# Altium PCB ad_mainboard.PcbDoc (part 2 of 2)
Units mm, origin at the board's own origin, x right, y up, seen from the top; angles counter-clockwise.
Board outline 51.7 x 87.6 mm, 4 copper layers (Top Layer, Layer 1, Layer 2, Bottom Layer), stack 0.568 mm thick; 187 components, 104 nets, 568 pads, 376 vias.
Unrouted connection lines stored in the file: 1.
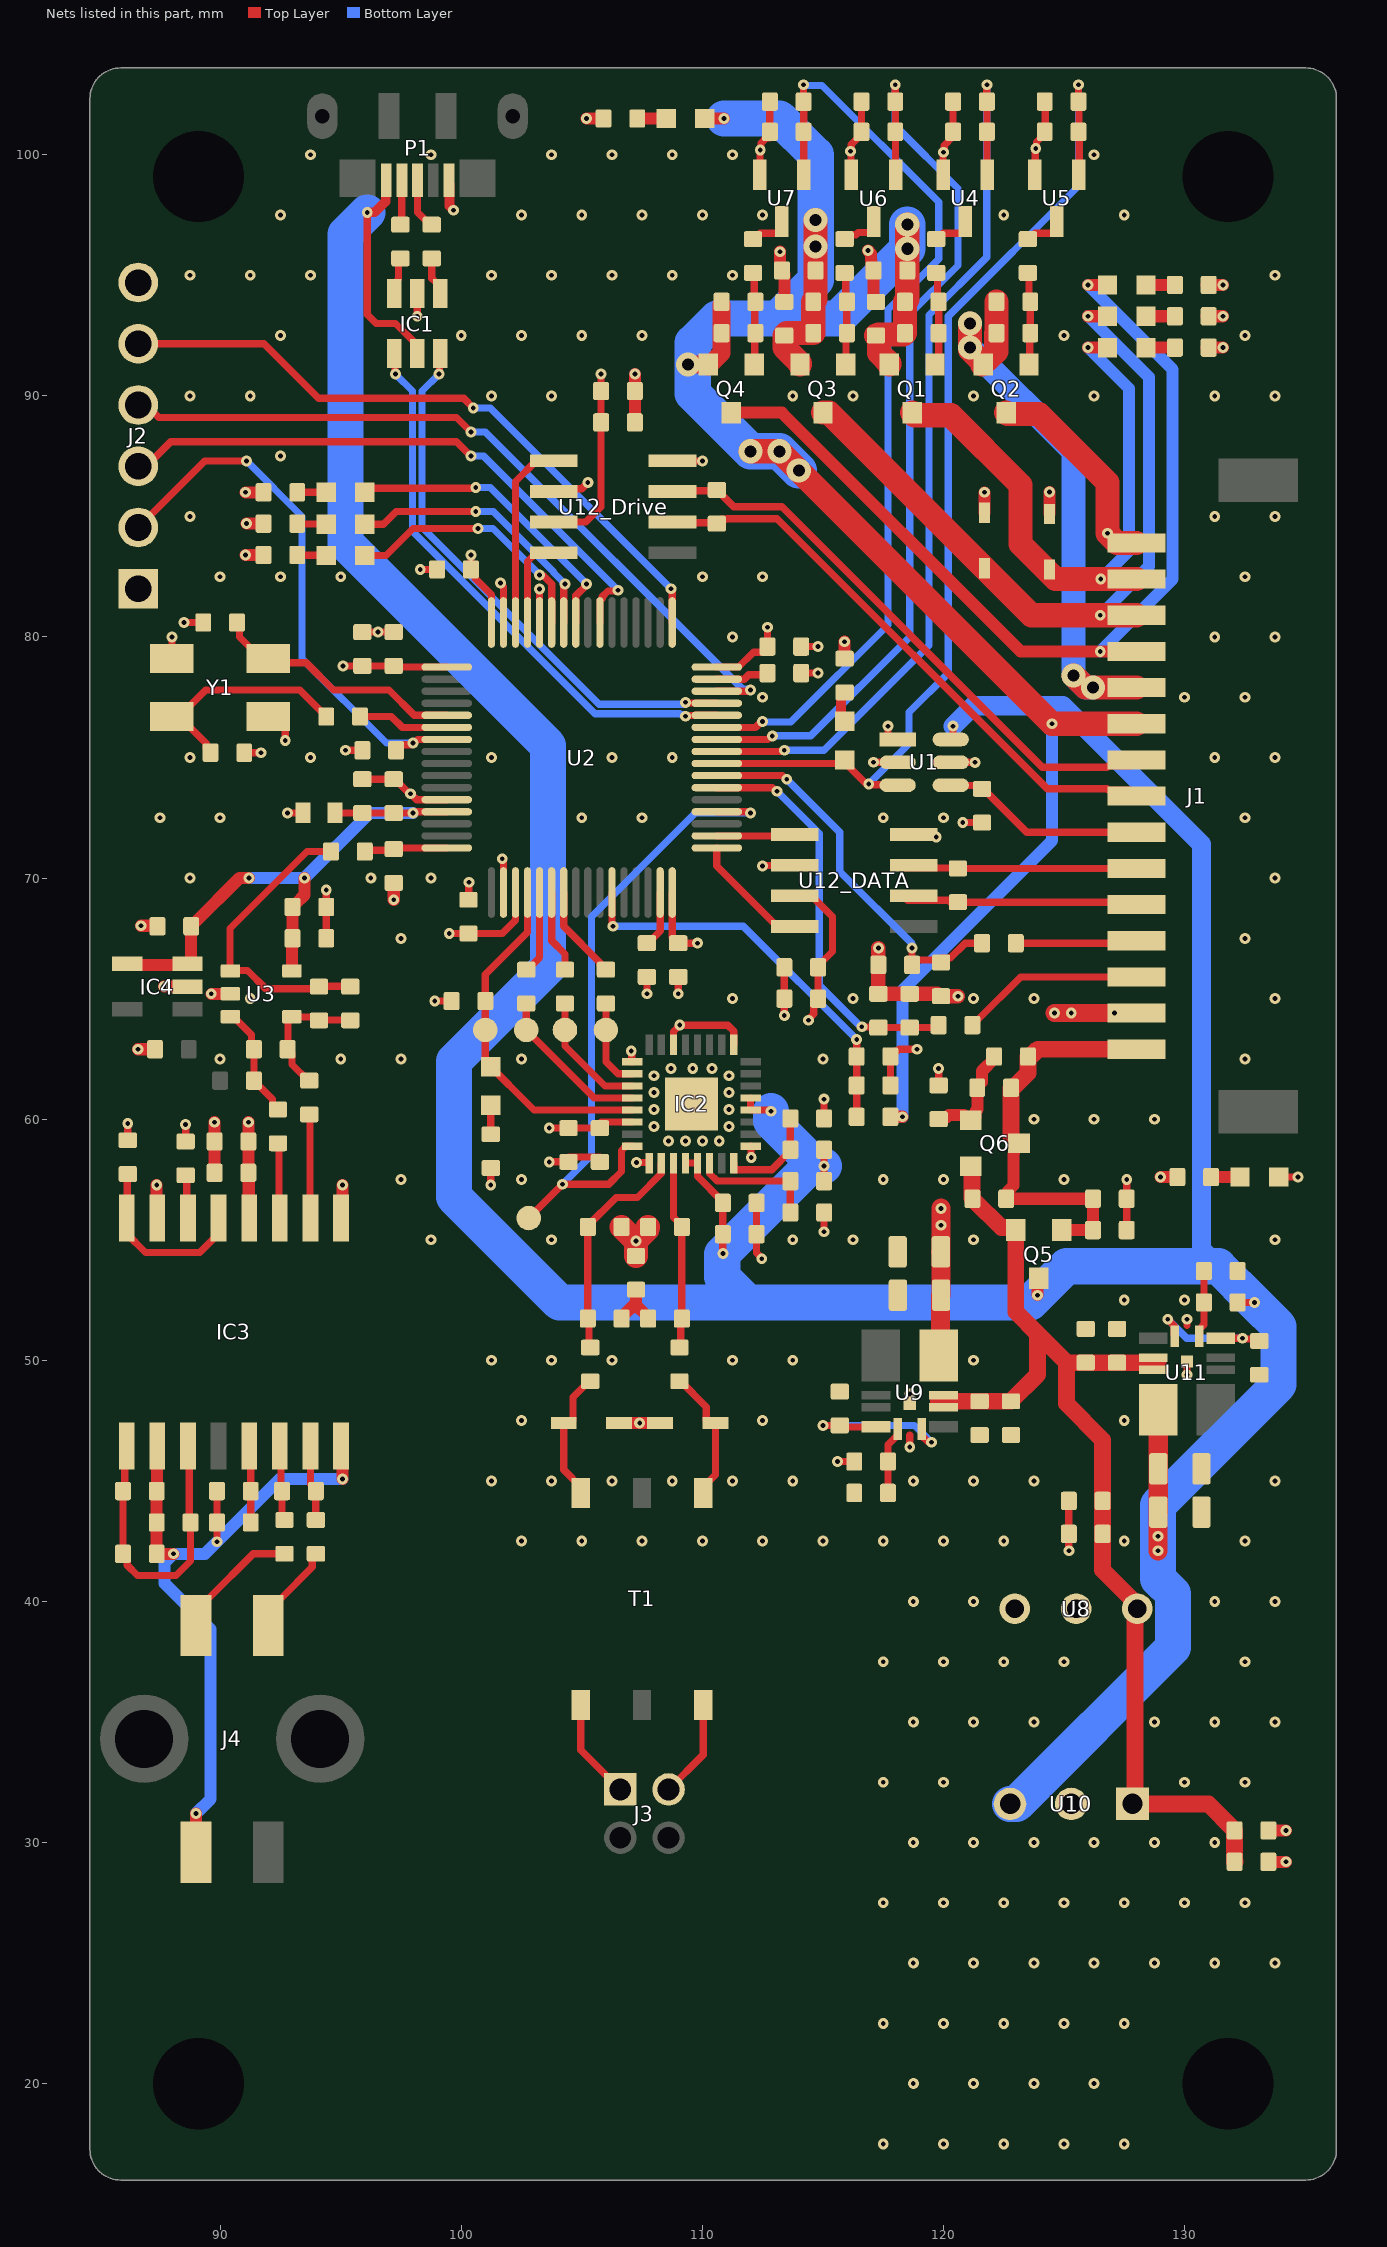
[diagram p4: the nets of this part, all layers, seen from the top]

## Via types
v1: diameter 0.45, hole 0.2, Top Layer to Bottom Layer, tented both sides, 364 vias
v2: diameter 1, hole 0.5, Top Layer to Bottom Layer, tented both sides, 12 vias

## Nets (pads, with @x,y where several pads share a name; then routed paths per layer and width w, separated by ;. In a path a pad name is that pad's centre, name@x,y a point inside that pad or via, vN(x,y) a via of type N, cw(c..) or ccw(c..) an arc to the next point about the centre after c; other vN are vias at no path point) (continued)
3V3: C2.2 C3.1 C4.1 C5.1 C6.1 C7.1 C18.2 C19.1 C27.2 C28.2 C57.2 C58.2 C67_DATA.2 C67_Drive.2 C68_DATA.1 C68_Drive.1 D14.2 IC2.1 IC2.6 IC2.25 IC2.30 IC3.12 J2.1 L1.1 R3.2 R19.2 R29.2 R57.2 U1.1 U1.5 U2.1 U2.19 U2.32 U2.48 U2.64 U8.3 U9.4 U12_DATA.3 U12_Drive.3 | length 56.9
  Top Layer w0.3: v1(88.57,59.775) R29.2@88.57,59.075 R29.2@88.62,59.075 ; v1(92.8,72.7) L1.1@93.437,72.7 ; v1(95.1,78.8) C2.2@95.9,78.8 C3.1@97.2,78.8 97.25,78.75 U2.1@99.4,78.75 ; v1(98.9,64.9) R3.2@99.6,64.9 ; v1(99.5,67.7) C4.1@100.3,67.7 101.7,67.7 102.25,68.25 U2.19@102.25,69.4 ; C7.1@100.4,82.8 v1(100.4,83.4) ; C7.1@100.58,82.911 100.58,82.42 101.25,81.75 U2.64@101.25,80.6 ; v1(101.225,57.275) R19.2@101.225,57.975 ; v1(103.65,59.63) C18.2@104.45,59.63 C19.1@105.75,59.63 ; U12_Drive.3@103.835,84.765 105.165,84.765 105.8,85.4 C68_Drive.1@105.8,88.9 C67_Drive.2@105.8,90.2 v1(105.8,90.9) ; C19.1@105.75,59.83 105.8,59.88 IC2.6@107.1,59.88 ; v1(107.05,62.83) 107.075,62.805 107.075,62.38 IC2.1@107.1,62.38 ; U2.32@108.75,69.4 108.75,67.55 108.77,67.53 108.77,67.48 108.95,67.3 C5.1@109,67.3 v1(109.8,67.3) ; IC2.30@108.8,63.28 108.8,63.639 v1(109.061,63.9) 111.054,63.9 111.3,63.654 IC2.25@111.3,63.08 ; U2.48@110.6,78.75 111.5,78.75 112.12,79.37 112.52,79.37 112.7,79.55 C6.1@112.7,79.6 v1(112.7,80.4) ; U12_DATA.3@113.5,69.16 114.665,69.16 114.675,69.15 114.675,69.125 115.4,68.4 115.4,66.95 114.8,66.35 C68_DATA.1@114.8,65 114.62,64.82 114.62,64.36 114.4,64.141 v1(114.4,64.1) ; v1(115.6,45.8) R57.2@116.3,45.8 ; U1.1@117.7,75.95 v1@117.7,76.3 ; U1.5@119.9,74.925 120.025,74.8 U1.5@120.771,74.8 ; U1.5@120.3,74.8 U1.5@120.771,74.8 ; v1(121.303,74.8) U1.5@120.771,74.8 ; D14.2@133.9,57.6 v1(134.7,57.6)
  Top Layer w0.5: v1(91.17,59.875) C27.2@91.17,59.075 C28.2@91.17,57.775 91.188,57.758 91.188,55.918 IC3.12@91.205,55.9
  Top Layer w0.8: U9.4@119.8,50.2 119.88,50.28 119.88,52.68 C57.2@119.9,52.7 119.895,52.705 119.895,54.495 C58.2@119.89,54.5 119.9,54.51 v1(119.9,55.6) v1(119.9,56.3)
  other v1: 117.7,76.3
3V3A: C8.2 C9.2 C25.2 C26.2 C40.2 IC4.3 IC4.4 L1.2 U2.13 U3.5 | length 24.2
  Top Layer w0.3: L1.2@94.763,72.7 C8.2@95.9,72.7 C9.2@97.2,72.7 v1(98,72.7) 98.041,72.7 98.091,72.75 U2.13@99.4,72.75
  Top Layer w0.5: IC4.4@85.844,66.4 IC4.3@88.6,66.4 ; IC4.3@88.796,66.4 88.8,66.404 C40.2@88.8,68 ; C40.2@88.8,68.05 88.88,68.13 88.93,68.13 90.8,70 v1(91.2,70) ; U3.5@92.975,66.15 92.988,66.163 92.988,67.487 C26.2@93,67.5 C25.2@93,68.8 93,68.85 93.08,68.93 93.13,68.93 93.5,69.3 v1(93.5,70)
  Bottom Layer w0.5: v1(91.2,70) v1(93.5,70) 96.2,72.7 v1(98,72.7)
5V: C20.2 C21.1 C64.2 C65.2 IC1.5 IC2.12 IC2.13 IC2.20 IC2.21 P1.1 Q5.3 R24.2 R25.2 R60.2 U1.6 U10.3 U11.4 | length 175.1
  Top Layer w0.3: v1(96.1,97.6) 96.1,93.375 96.475,93 97.275,93 98.025,92.25 98.025,91.9 IC1.5@98.175,91.75 ; IC2.12@109.3,58.18 IC2.13@109.8,58.18 109.8,57.63 110.85,56.58 C21.1@110.85,56.53 C20.2@110.85,55.23 v1(110.85,54.43) ; IC2.21@112,60.88 IC2.20@112,60.38 112.759,60.38 112.809,60.33 v1(112.85,60.33) ; R24.2@115.05,57.43 v1(115.05,58.055) R25.2@115.05,58.73 ; U1.6@120.3,75.75 120.4,75.85 v1(120.4,76.3) ; R60.2@132.2,52.4 v1(132.9,52.4)
  Top Layer w0.4: v1(96.1,97.6) 96.11,97.61 96.41,97.61 96.863,98.063 P1.1@96.863,98.765
  Top Layer w0.5: v1(123.9,52.7) 123.9,53.35 Q5.3@123.95,53.4
  Top Layer w0.8: v1(128.9,42.1) v1(128.9,42.7) 128.9,43.69 C64.2@128.91,43.7 C65.2@128.91,45.5 128.905,45.505 128.905,47.945 U11.4@128.9,47.95
  Bottom Layer w0.8: v1(120.4,76.3) 121.252,77.152 124.948,77.152 130.7,71.4 130.7,54.6 131.4,53.9
  Bottom Layer w1.5: v1(96.1,97.6) 95.2,96.7 95.2,83.9 103.6,75.5 103.6,66.3 99.7,62.4 99.7,56.773 104.073,52.4 111.873,52.4 ; v1@110.823,54.403 110.823,53.45 111.873,52.4 ; v1(110.85,54.43) 114.475,58.055 114.723,58.055 ; v1(112.85,60.33) 112.85,59.928 114.723,58.055 ; v1(115.05,58.055) 114.723,58.055 ; U10.3@122.76,31.6 123.033,31.6 129.527,38.093 129.527,40.316 128.9,40.942 v1(128.9,42.1) v1(128.9,42.7) 128.9,44 133.9,49 133.9,51.4 v1(132.9,52.4) 131.4,53.9 125.1,53.9 v1(123.9,52.7) 123.6,52.4 111.873,52.4
6822_State: IC2.8 TP5.1 U2.36 | length 27.4
  Top Layer w0.3: TP5.1@102.8,55.9 v1(104.2,57.3) 106.12,57.3 106.65,57.83 106.65,58.705 106.825,58.88 IC2.8@107.1,58.88 ; U2.36@110.6,72.75 111.909,72.75 111.959,72.7 v1(112,72.7)
  Bottom Layer w0.3: v1(104.2,57.3) 105.4,58.5 105.4,68.4 109.7,72.7 v1(112,72.7)
BMS_SD_IN: C43.2 J1.5 Q2.2 R39.2 | length 25
  Top Layer w1: v2(121.1,93) v2(121.1,92) 121.1,91.902 121.6,91.402 121.6,91.302 121.8,91.502 121.85,91.502 122.189,91.84 C43.2@122.189,92.59 ; C43.2@122.2,92.602 R39.2@122.2,93.902 ; v2(125.4,78.4) 125.9,77.9 v2(126.2,77.9) J1.5@128,77.9
  Bottom Layer w1: v2(121.1,93) v2(121.1,92) 125.4,87.7 v2(125.4,78.4) 125.9,77.9 v2(126.2,77.9)
BMS_SD_OUT: J1.1 Q2.3 | length 9.7
  Top Layer w1: Q2.3@122.6,89.302 122.656,89.245 123.955,89.245 126.8,86.4 v1(126.8,84.3) J1.1@127.2,83.9 ; J1.1@127.2,83.9 J1.1@128,83.9 J1.1@127.2,83.9
BMS_Status: C45.2 D1.2 R42.2 U1.3 U2.40 U5.1 | length 43.7
  Top Layer w0.3: U2.40@110.6,74.75 113.579,74.75 113.583,74.754 114.6,74.754 115.5,74.754 115.946,74.754 116.771,73.929 116.871,73.929 116.925,73.875 117.69,73.875 U1.3@117.715,73.9 ; R42.2@125.6,102.202 v1(125.6,102.902) ; R42.2@125.625,102.254 125.625,100.954 125.633,100.947 125.633,99.332 U5.1@125.64,99.325
  Bottom Layer w0.3: v1(116.9,73.9) 118.575,75.575 118.575,76.875 120.2,78.5 120.2,93.3 125.6,98.7 v1(125.6,102.902)
BMS_Status_Out: C1.1 J1.9 U1.4 | length 8.9
  Top Layer w0.3: U1.4@119.928,73.9 119.991,73.837 121.37,73.837 121.507,73.7 121.65,73.7 123.45,71.9 J1.9@128,71.9
CAN_RX_DATA: U2.33 U12_DATA.4 | length 4.7
  Top Layer w0.3: U2.33@110.6,71.25 110.6,70.5 112.99,68.11 113.28,68.11 U12_DATA.4@113.5,67.89
CAN_RX_Drive: U2.61 U12_Drive.4 | length 3.8
  Top Layer w0.3: U2.61@102.75,80.6 102.75,81.783 102.746,81.787 102.746,83.131 103.11,83.495 U12_Drive.4@103.835,83.495
CAN_TX_DATA: U2.34 U12_DATA.1 | length 2.9
  Top Layer w0.3: U2.34@110.6,71.75 113.45,71.75 U12_DATA.1@113.5,71.7
CAN_TX_Drive: U2.62 U12_Drive.1 | length 7.8
  Top Layer w0.3: U2.62@102.25,80.6 102.25,86.445 103.11,87.305 U12_Drive.1@103.835,87.305
CANH_Data_P: J1.10 R62_DATA.2 U12_DATA.7 | length 8.7
  Top Layer w0.3: U12_DATA.7@118.43,70.43 118.445,70.415 120.285,70.415 120.3,70.4 J1.10@127.075,70.4
CANH_Drive_P: J1.7 R62_Drive.2 U12_Drive.7 | length 24.1
  Top Layer w0.3: U12_Drive.7@108.765,86.035 108.797,86.067 110.567,86.067 R62_Drive.2@110.6,86.1 111.3,85.4 113.3,85.4 124.1,74.6 126.774,74.6 126.824,74.65 127.75,74.65 J1.7@128,74.9
CANL_Data_N: J1.11 R62_DATA.1 U12_DATA.6 | length 9.4
  Top Layer w0.3: U12_DATA.6@118.43,69.16 118.51,69.08 120.22,69.08 R62_DATA.1@120.3,69 ; R62_DATA.1@120.6,69 127.9,69 J1.11@128,68.9
CANL_Drive_N: J1.8 R62_Drive.1 U12_Drive.6 | length 24.1
  Top Layer w0.3: U12_Drive.6@108.765,84.765 108.797,84.732 R62_Drive.1@110.617,84.732 ; R62_Drive.1@110.6,84.7 110.78,84.88 110.986,84.88 111.006,84.9 113.1,84.9 124.3,73.7 126.774,73.7 126.824,73.65 127.75,73.65 J1.8@128,73.4
Charger: J1.13 R7.2 | length 7.7
  Top Layer w0.3: R7.2@121.2,63.9 121.2,63.95 121.38,64.13 121.43,64.13 123.2,65.9 J1.13@128,65.9
Charger_mcu: C10.1 R7.1 R8.1 U2.38 | length 16.8
  Top Layer w0.3: U2.38@110.6,73.75 112.909,73.75 113.059,73.6 v1(113.1,73.6) ; v1(116.614,63.836) 116.632,63.818 117.282,63.818 C10.1@117.3,63.8 119.7,63.8 R7.1@119.8,63.9
  Bottom Layer w0.3: v1(113.1,73.6) 114.85,71.85 114.85,65.55 v1@116.445,63.955
Contactor_N: D9.1 D11.2 J1.2 Q1.3 | length 25.2
  Top Layer w0.5: v1(126,92) D11.2@126.8,92
  Top Layer w1: Q1.3@118.7,89.302 118.806,89.195 120.305,89.195 123.2,86.3 123.2,83.85 124.65,82.4 J1.2@128,82.4
  Bottom Layer w0.5: v1(126,92) 127.7,90.3 127.7,83.575 v1(126.525,82.4)
Contactor_N_ctr: C44.2 R40.2 U2.41 U4.1 | length 38.5
  Top Layer w0.3: U2.41@110.6,75.25 113.309,75.25 113.359,75.3 v1(113.4,75.3) ; v1(121.8,102.902) R40.2@121.8,102.202 121.807,102.194 121.807,99.28 U4.1@121.815,99.272
  Bottom Layer w0.3: v1(113.4,75.3) 115.043,75.3 119.4,79.657 119.4,93.352 121.8,95.752 v1(121.8,102.902)
Contactor_P: D10.1 D12.2 J1.3 Q3.3 | length 31.6
  Top Layer w0.5: v1(126,93.3) D12.2@126.8,93.3
  Top Layer w1: Q3.3@115,89.302 115.248,89.302 D10.1@121.7,82.85 123.65,80.9 v1(126.5,80.9) J1.3@128,80.9
  Bottom Layer w0.5: v1(126,93.3) 128.52,90.78 128.52,82.92 v1(126.5,80.9)
Contactor_P_ctrl: C48.2 R46.2 U2.42 U6.1 | length 38.2
  Top Layer w0.3: U2.42@110.6,75.75 112.713,75.75 112.861,75.898 v1(112.902,75.898) ; v1(118,102.902) R46.2@118,102.202 118.007,102.194 118.007,99.28 U6.1@118.015,99.272
  Bottom Layer w0.3: v1(112.902,75.898) 114.498,75.898 118.6,80 118.6,93.402 120.6,95.402 120.6,98.6 118,101.2 v1(118,102.902)
Contactor_Pre: D13.2 J1.4 Q4.3 | length 38.7
  Top Layer w0.5: Q4.3@111.2,89.302 113.298,89.302 123.2,79.4 v1(126.5,79.4) J1.4@127.075,79.4 ; v1(126,94.6) D13.2@126.8,94.6
  Bottom Layer w0.5: v1(126,94.6) 129.5,91.1 129.5,82.4 v1(126.5,79.4)
Contactor_Pre_ctr: C50.2 R52.2 U2.43 U7.1 | length 38.5
  Top Layer w0.3: U2.43@110.6,76.25 112.209,76.25 112.459,76.5 v1(112.5,76.5) ; v1(114.2,102.902) R52.2@114.2,102.202 114.207,102.194 114.207,99.28 U7.1@114.215,99.272
  Bottom Layer w0.3: v1(112.5,76.5) 112.529,76.471 113.671,76.471 117.7,80.5 117.7,93.576 119.8,95.676 119.8,98.04 114.967,102.873 114.228,102.873 v1(114.2,102.902)
CSB: D6.1 IC2.5 R3.1 TP4.1 U2.20 | length 14.7
  Top Layer w0.3: U2.20@102.75,69.4 102.75,67.75 101,66 R3.1@101,64.9 101,62.4 103.02,60.38 IC2.5@107.1,60.38
Current_ADC: C35.2 R31.1 U2.16 | length 3.5
  Top Layer w0.3: R31.1@96,71.1 96.05,71.15 97.15,71.15 97.2,71.1 97.35,71.25 U2.16@99.4,71.25
GND: C1.2 C2.1 C3.2 C4.2 C5.2 C6.2 C7.2 C8.1 C9.1 C10.2 C11.1 C12.1 C13.2 C14.2 C15.2 C16.2 C17.2 C18.1 C19.2 C20.1 C21.2 C22.2 C23.1 C24.2 C25.1 C26.1 C27.1 C28.1 C33.2 C35.1 C39.1 C40.1 C42.1 C44.1 C45.1 C47.1 C48.1 C50.1 C51.2 C52.1 C53.2 C54.1 C55.2 C57.1 C58.1 C59.1 C60.1 C61.2 C62.1 C63.2 C64.1 C65.1 C66.1 C67_DATA.1 C67_Drive.1 C68_DATA.2 C68_Drive.2 D7.1 D8.2 D9.2 D10.2 IC1.2 IC2.9 IC2.17 IC2.33 IC3.9 IC3.15 IC4.2 J1.14 J2.6 P1.5 R8.2 R11.1 R12.1 R13.1 R15.1 R16.1 R17.1 R18.1 R26.2 R27.1 R37.1 R40.1 R42.1 R44.1 R46.1 R48.1 R49.1 R50.1 R52.1 R53.1 R55.1 R58.1 R59.1 R61.1 U1.2 U2.12 U2.18 U2.60 U2.63 U3.2 U4.2 U5.2 U6.2 U7.2 U8.2 U9.10 U10.2 U11.10 U12_DATA.2 U12_DATA.8 U12_Drive.2 U12_Drive.8 Y1.2 Y1.4 | length 96.7
  Top Layer w0.3: C33.2@86.17,59.125 v1(86.17,59.825) ; Y1.4@88,79.1 v1(88,80) ; v1(88.5,80.6) C12.1@89.3,80.6 ; U3.2@90.4,65.2 U3.2@90.404,65.204 ; C11.1@91,75.2 v1(91.7,75.2) ; Y1.2@92,76.7 92.25,76.7 92.7,76.25 v1(92.7,75.7) ; C26.1@94.4,67.5 C25.1@94.4,68.8 v1(94.4,69.5) ; v1(95.2,75.3) C13.2@95.9,75.3 ; C8.1@95.9,74.1 C9.1@97.2,74.1 ; C2.1@95.9,80.2 v1(96.55,80.2) C3.2@97.2,80.2 ; C9.1@97.25,74.1 97.821,73.529 97.871,73.529 v1(97.9,73.5) 98.15,73.25 U2.12@99.4,73.25 ; v1(98.175,93.3) IC1.2@98.175,94.224 ; v1(98.3,82.8) C7.2@99,82.8 ; C4.2@100.3,69.1 100.313,69.113 100.313,69.813 v1(100.326,69.826) ; v1(101.634,82.234) 101.634,82.194 101.75,82.078 U2.63@101.75,80.6 ; v1(101.7,70.8) 101.7,70.759 101.75,70.709 U2.18@101.75,69.4 ; v1(103.248,81.989) 103.25,81.987 U2.60@103.25,80.6 ; v1(103.65,58.23) C18.1@104.45,58.23 ; U12_Drive.2@103.835,86.035 103.95,86.15 104.999,86.15 v1(105.25,86.4) ; C18.1@104.45,58.43 C19.2@105.75,58.43 ; v1(107.275,58.205) 107.28,58.199 107.8,58.199 IC2.9@107.8,58.18 ; v1(107.7,65.2) C16.2@107.7,65.9 ; U12_Drive.8@108.765,87.305 108.767,87.303 109.997,87.303 v1(110,87.3) ; v1(109,65.2) C5.2@109,65.9 ; IC2.17@112,58.88 112.013,58.88 112.013,58.419 v1(112.025,58.407) ; C21.2@112.25,56.53 C20.1@112.25,55.23 112.25,54.459 112.466,54.243 v1(112.466,54.214) ; U7.2@112.387,99.132 112.392,99.138 112.392,100.194 v1(112.4,100.202) 112.429,100.23 112.429,100.48 112.653,100.704 112.794,100.704 R52.1@112.794,102.054 ; v1(112.5,70.5) 112.517,70.517 113.398,70.517 U12_DATA.2@113.415,70.5 ; v1(113.4,64.3) C68_DATA.2@113.4,65 C67_DATA.1@113.4,66.3 ; C15.2@114.1,78.5 v1(114.8,78.5) ; C6.2@114.1,79.6 v1(114.8,79.6) ; v1(115.05,55.33) R26.2@115.05,56.13 ; R27.1@115.05,60.03 v1(115.05,60.83) ; v1(116.145,100.147) v1@116.192,100.147 ; U6.2@116.185,99.374 116.165,99.394 116.165,100.119 v1@116.192,100.147 ; R46.1@116.6,102.332 116.6,100.852 116.174,100.425 116.174,100.165 v1@116.192,100.147 ; v1(117.093,74.803) 117.095,74.802 117.7,74.802 U1.2@117.702,74.803 ; R11.1@117.8,61.4 C14.2@117.8,62.7 ; C14.2@117.8,62.6 117.8,62.65 117.98,62.83 118.09,62.83 118.156,62.896 v1@118.876,62.896 ; U12_DATA.8@118.43,71.7 v1(119.7,71.7) ; v1(118.6,46.4) 118.6,46.9 ; U9.10@118.6,48.195 v1(118.6,48.6) ; R58.1@119.808,61.408 119.8,61.417 119.8,62.083 v1@119.808,62.092 ; U4.2@119.97,99.203 119.985,99.218 119.985,100.088 v1(120,100.103) 120.029,100.132 120.029,100.382 120.4,100.753 R40.1@120.4,102.103 ; v1(120.8,72.3) C1.2@121.6,72.3 ; U5.2@123.795,99.354 123.81,99.369 123.81,100.239 v1(123.825,100.254) 123.854,100.283 123.854,100.533 124.225,100.904 R42.1@124.225,102.254 ; v1(125.2,42.1) C52.1@125.2,42.8 C53.2@125.2,44.168 ; C51.2@127.6,55.4 v1(127.6,57.5) ; v1(130.1,49.4) U11.10@130.1,49.955 ; 130.1,51.45 v1(130.1,51.7)
  Top Layer w0.4: P1.5@99.512,98.765 99.512,97.877 99.675,97.714 v1(99.675,97.7)
  Top Layer w0.5: v1(86.6,62.9) C39.1@87.3,62.9 ; v1(86.722,68.022) 87.378,68.022 C40.1@87.4,68 ; v1(87.37,57.275) 87.37,55.925 IC3.15@87.395,55.9 ; v1(87.675,65.5) IC4.2@88.65,65.5 ; v1(89.634,65.2) U3.2@90.425,65.2 ; C28.1@89.77,57.775 C27.1@89.77,59.075 v1(89.77,59.875) ; v1(91.052,83.4) R17.1@91.8,83.4 ; v1(91.052,86) R16.1@91.8,86 ; v1(91.1,84.7) R12.1@91.8,84.7 ; IC3.9@95.015,55.9 95.07,55.955 v1(95.07,57.275) ; v1(97.2,69.1) C35.1@97.2,69.8 ; v1(105.2,101.5) R15.1@105.9,101.5 ; D7.1@106.55,47.4 v1(107.4,47.4) D8.2@108.25,47.4 ; C68_Drive.2@107.2,88.9 C67_Drive.1@107.2,90.2 v1(107.2,90.9) ; v1(113.221,95.979) 113.221,95.279 R44.1@113.3,95.2 113.3,95.15 113.4,95.05 C47.1@113.4,93.9 ; R13.1@115.9,79.1 v1(115.9,79.8) ; v1(116.871,96.029) 117,95.9 117,95.608 117.02,95.588 117.02,95.28 R37.1@117.1,95.2 ; R37.1@117.1,95.15 117.1,93.98 117.18,93.9 C42.1@117.2,93.9 ; D10.2@121.7,85.15 v1(121.7,86) ; D9.2@124.4,85.1 v1(124.4,86.015) ; v1(129,57.6) R55.1@129.7,57.6 ; R48.1@130.9,92 v1(131.6,92) ; R49.1@130.9,93.3 v1(131.6,93.3) ; R50.1@130.9,94.6 v1(131.6,94.6) ; C61.2@133.475,29.2 v1(134.2,29.2) ; C60.1@133.475,30.5 v1(134.2,30.5)
  Top Layer w0.6: C10.2@117.3,65.2 R8.2@118.6,65.2 119.75,65.2 119.85,65.1 R18.1@119.9,65.1 v1(120.6,65.1) ; C10.2@117.3,65.4 C17.2@117.3,66.6 ; C17.2@117.3,66.4 v1(117.3,67.1)
  Top Layer w0.75: v1(124.6,64.4) v1(125.3,64.4) v1(127.1,64.4)
  Top Layer w1: C22.2@106.65,55.53 107.23,54.95 v1(107.25,54.95) ; C24.2@107.25,54.33 v1(107.25,54.95) ; C23.1@107.75,55.53 107.73,55.51 107.73,55.43 v1(107.25,54.95)
  other v1: 117.5,17.5 120,17.5 122.5,17.5 125,17.5 127.5,17.5 118.75,20 121.25,20 123.75,20 126.25,20 117.5,22.5 120,22.5 122.5,22.5 125,22.5 127.5,22.5 118.75,25 121.25,25 123.75,25 126.25,25 128.75,25 131.25,25 133.75,25 117.5,27.5 120,27.5 122.5,27.5 125,27.5 127.5,27.5 130,27.5 132.5,27.5 118.75,30 121.25,30 123.75,30 126.25,30 128.75,30 131.25,30 117.5,32.5 120,32.5 130,32.5 132.5,32.5 118.75,35 121.25,35 123.75,35 128.75,35 131.25,35 133.75,35 117.5,37.5 120,37.5 122.5,37.5 125,37.5 132.5,37.5 118.75,40 121.25,40 131.25,40 133.75,40 102.5,42.5 105,42.5 107.5,42.5 110,42.5 112.5,42.5 115,42.5 117.5,42.5 120,42.5 122.5,42.5 127.5,42.5 132.5,42.5 101.25,45 103.75,45 106.25,45 108.75,45 111.25,45 113.75,45 118.75,45 121.25,45 123.75,45 133.75,45 102.5,47.5 112.5,47.5 127.5,47.5 101.25,50 103.75,50 106.25,50 111.25,50 113.75,50 121.25,50 127.5,52.5 130,52.5 98.75,55 103.75,55 113.75,55 116.25,55 121.25,55 133.75,55 97.5,57.5 102.5,57.5 117.5,57.5 120,57.5 125,57.5 108.6,59.1 109.3,59.1 110,59.1 110.7,59.1 108,59.7 111.1,59.7 123.75,60 126.25,60 128.75,60 108,60.4 111.1,60.4 108,61.1 111.1,61.1 108,61.8 111.1,61.8 108.7,62.1 109.6,62.1 110.4,62.1 119.8,62.1 90,62.5 95,62.5 97.5,62.5 102.5,62.5 115,62.5 132.5,62.5 118.902,62.9 91.25,65 111.25,65 116.25,65 121.25,65 123.75,65 133.75,65 97.5,67.5 132.5,67.5 88.75,70 96.25,70 98.75,70 133.75,70 87.5,72.5 90,72.5 105,72.5 107.5,72.5 117.5,72.5 120,72.5 132.5,72.5 88.75,75 93.75,75 101.25,75 106.25,75 108.75,75 131.25,75 133.75,75 112.5,77.5 130,77.5 132.5,77.5 111.25,80 131.25,80 133.75,80 90,82.5 92.5,82.5 95,82.5 110,82.5 112.5,82.5 132.5,82.5 88.75,85 131.25,85 133.75,85 92.5,87.5 88.75,90 91.25,90 101.25,90 103.75,90 113.75,90 116.25,90 121.25,90 126.25,90 131.25,90 133.75,90 92.5,92.5 100,92.5 102.5,92.5 105,92.5 107.5,92.5 125,92.5 132.5,92.5 88.75,95 91.25,95 93.75,95 101.25,95 103.75,95 106.25,95 108.75,95 111.25,95 133.75,95 92.5,97.5 102.5,97.5 105,97.5 107.5,97.5 110,97.5 112.5,97.5 122.5,97.5 127.5,97.5 93.75,100 98.75,100 103.75,100 106.25,100 108.75,100 111.25,100 126.25,100
GPIO_LED_1: D4.2 U2.57 | length 12.7
  Top Layer w0.3: D4.2@96,86 96.171,86.171 100.571,86.171 v1(100.6,86.2) ; U2.57@104.75,80.6 104.75,81.709 105.2,82.159 v1(105.2,82.2)
  Bottom Layer w0.3: v1(100.6,86.2) 101.2,86.2 v1(105.2,82.2)
GPIO_LED_2: D2.2 U2.58 | length 11.4
  Top Layer w0.3: D2.2@96,84.675 96.775,84.675 97.3,85.2 v1(100.6,85.2) ; U2.58@104.25,80.6 104.25,82.109 104.3,82.159 v1(104.3,82.2)
  Bottom Layer w0.3: v1(100.6,85.2) 101.328,85.2 103.823,82.706 103.823,82.677 v1(104.3,82.2)
GPIO_LED_3: D5.2 U2.59 | length 10.8
  Top Layer w0.3: D5.2@96,83.375 96.875,83.375 98,84.5 v1(100.7,84.5) ; v1(103.252,82.566) 103.281,82.538 103.41,82.538 103.75,82.197 U2.59@103.75,80.6
  Bottom Layer w0.3: v1(100.7,84.5) 101.318,84.5 v1(103.252,82.566)
HSE_IN: C12.2 U2.5 Y1.3 | length 10.6
  Top Layer w0.3: C12.2@90.7,80.6 90.799,80.501 90.799,80.001 91.7,79.1 Y1.3@92,79.1 92.174,78.926 93.574,78.926 94.7,77.8 97,77.8 98.05,76.75 U2.5@99.4,76.75
HSE_OUT: R9.2 U2.6 | length 3.8
  Top Layer w0.3: R9.2@95.8,76.7 97.1,76.7 97.55,76.25 U2.6@99.4,76.25
IM: C22.1 IC2.10 R20.2 R22.2 | length 9.4
  Top Layer w0.3: C22.1@105.25,55.53 R20.2@105.25,51.73 105.3,51.68 105.3,50.58 R22.2@105.35,50.53 ; C22.1@105.25,55.58 106.425,56.754 107.305,56.754 108.3,57.749 IC2.10@108.3,58.18
IM_Out: J3.1 T1.4 | length 4.2
  Top Layer w0.3: T1.4@104.96,35.7 104.96,33.84 J3.1@106.6,32.2
IMD_Status: J1.12 R14.2 | length 5
  Top Layer w0.3: R14.2@123,67.3 127.9,67.3 J1.12@128,67.4
IMD_Status_mcu: C17.1 R14.1 R18.2 U2.39 | length 15.9
  Top Layer w0.3: U2.39@110.6,74.25 113.309,74.25 113.459,74.1 v1(113.5,74.1) ; C17.1@118.7,66.4 v1(118.7,67.1) ; C17.1@118.7,66.6 119.8,66.6 R18.2@119.9,66.5 ; R18.2@119.85,66.65 119.88,66.68 120.28,66.68 120.9,67.3 R14.1@121.6,67.3
  Bottom Layer w0.3: v1(113.5,74.1) 115.7,71.9 115.7,70.273 v1@118.7,67.273
IP: C23.2 IC2.11 R21.1 R23.2 | length 7.8
  Top Layer w0.3: IC2.11@108.8,58.18 108.8,55.93 109.15,55.58 C23.2@109.15,55.53 R21.1@109.15,51.73 109.1,51.68 109.1,50.58 R23.2@109.05,50.53
IP_Out: J3.3 T1.6 | length 4.1
  Top Layer w0.3: J3.3@108.6,32.2 110.04,33.64 T1.6@110.04,35.7
MISO: IC2.3 R5.1 TP2.1 | length 5.2
  Top Layer w0.3: R5.1@104.3,64.8 TP2.1@104.3,63.7 104.3,63.038 105.958,61.38 IC2.3@107.1,61.38
MOSI: IC2.2 R6.1 TP1.1 | length 3.7
  Top Layer w0.3: R6.1@106,64.8 106,62.38 106.5,61.88 IC2.2@107.1,61.88
NetC11_2: C11.2 R9.1 Y1.1 | length 9.4
  Top Layer w0.3: Y1.1@88,76.7 Y1.1@88.3,76.7 ; C11.2@89.6,75.2 89.42,75.38 89.42,75.58 Y1.1@88.3,76.7 ; R9.1@94.396,76.704 94.396,76.754 94.22,76.93 94.17,76.93 93.3,77.8 89.4,77.8 Y1.1@88.3,76.7
NetC15_1: C15.1 U2.47 | length 2.2
  Top Layer w0.3: U2.47@110.6,78.25 111.74,78.25 111.92,78.43 112.63,78.43 C15.1@112.7,78.5
NetC16_1: C16.1 U2.31 | length 2.4
  Top Layer w0.3: C16.1@107.7,67.3 107.75,67.3 108.25,67.8 U2.31@108.25,69.4
NetC24_1: C24.1 R20.1 R21.2 | length 2.3
  Top Layer w0.5: R20.1@106.65,51.73 106.65,51.78 107.25,52.38 ; C24.1@107.25,52.93 107.25,52.38 ; R21.2@107.75,51.73 107.75,51.78 107.25,52.28 107.25,52.38
NetC29_1: C29.1 C34.2 R28.1 R30.2 U3.4 | length 5.4
  Top Layer w0.3: C34.2@92.8,62.9 92.98,62.72 92.98,62.27 93.65,61.6 R30.2@93.7,61.6 ; C34.2@92.813,63.123 92.813,64.238 94.063,64.238 C29.1@94.088,64.213 ; C29.1@94.088,64.113 R28.1@95.388,64.113
NetC29_2: C29.2 R28.2 R31.2 U3.1 | length 12.6
  Top Layer w0.3: C29.2@94.088,65.513 R28.2@95.388,65.513 ; C29.2@94.088,65.562 93.938,65.413 91.888,65.413 91.138,66.163 90.413,66.163 90.413,67.913 93.6,71.1 R31.2@94.6,71.1
NetC30_2: C30.2 C31.2 C32.2 IC3.1 IC3.3 | length 13
  Top Layer w0.3: C30.2@85.97,41.925 C31.2@85.97,44.575 86.048,44.653 86.048,46.373 IC3.1@86.125,46.45 ; C30.2@85.97,41.975 86.15,41.795 86.15,41.495 86.57,41.075 88.17,41.075 88.77,41.675 C32.2@88.77,43.275 88.718,43.328 88.718,46.398 IC3.3@88.665,46.45
NetC33_1: C33.1 IC3.13 IC3.16 | length 7.7
  Top Layer w0.3: C33.1@85.97,57.875 C33.1@86.048,57.798 ; C33.1@86.17,57.725 86.148,57.703 86.148,55.923 IC3.16@86.125,55.9 86.125,55.25 86.9,54.475 89.16,54.475 89.935,55.25 IC3.13@89.935,55.9
NetC34_1: C34.1 R32.2 R34.2 U3.3 | length 4.7
  Top Layer w0.3: U3.3@90.538,64.262 90.675,64.125 91.301,63.499 91.301,62.999 C34.1@91.4,62.9 R34.2@91.4,61.55 ; R34.2@91.4,61.6 R34.2@91.4,61.55 ; R32.2@92.4,60.4 92.35,60.4 92.17,60.58 92.17,60.83 91.63,61.37 91.58,61.37 R34.2@91.4,61.55
NetC36_1: C36.1 IC3.7 R35.2 | length 3.1
  Top Layer w0.3: IC3.7@93.745,46.45 93.745,44.85 C36.1@93.97,44.625 ; R35.2@93.97,43.375 C36.1@93.97,44.575
NetC36_2: C36.2 IC3.6 R33.2 | length 3.2
  Top Layer w0.3: IC3.6@92.473,46.448 IC3.6@92.475,46.45 92.523,46.403 92.523,44.623 C36.2@92.57,44.575 92.57,43.475 R33.2@92.67,43.375
NetC37_1: C37.1 C38.2 IC3.5 | length 3.2
  Top Layer w0.3: IC3.5@91.205,46.45 91.27,46.385 C37.1@91.27,43.275
NetC41_1: C41.1 Q1.1 R36.1 R38.2 | length 3.8
  Top Layer w0.3: Q1.1@119.65,91.378 119.8,91.528 R36.1@119.8,93.901 119.75,93.952 119.75,95.052 R38.2@119.7,95.102
NetC43_1: C43.1 Q2.1 R39.1 R41.2 | length 3.9
  Top Layer w0.3: R41.2@123.5,95.102 123.55,95.052 123.55,93.952 R39.1@123.6,93.902 ; Q2.1@123.55,91.302 123.575,91.327 123.575,92.577 C43.1@123.6,92.602 R39.1@123.6,93.902 ; R39.1@123.6,93.951 R39.1@123.6,93.902
NetC46_1: C46.1 Q3.1 R43.1 R45.2 | length 3.8
  Top Layer w0.3: R45.2@115.9,95.101 115.95,95.051 115.95,93.952 R43.1@116,93.901 ; Q3.1@115.935,91.303 115.96,91.328 115.96,92.578 C46.1@115.985,92.603 ; C46.1@115.985,92.703 R43.1@115.985,93.901
NetC49_1: C49.1 Q4.1 R47.1 R51.2 | length 3.9
  Top Layer w0.3: R51.2@112.1,95.102 112.15,95.052 112.15,93.952 R47.1@112.2,93.902 ; Q4.1@112.15,91.302 112.175,91.327 112.175,92.571 112.169,92.577 R47.1@112.169,93.952
NetC56_2: C56.2 Q6.1 R56.1 R58.2 | length 4.6
  Top Layer w0.5: R58.2@119.8,60 119.88,60.08 120.128,60.08 120.223,60.175 120.857,60.175 121.082,59.95 Q6.1@121.132,59.95 121.182,59.95 121.332,60.1 121.332,60.317 121.408,60.393 C56.2@121.408,61.358 ; C56.2@121.4,61.3 121.4,61.35 C56.2@121.408,61.358 ; C56.2@121.408,61.392 C56.2@121.408,61.358 ; R56.1@122.1,62.5 121.6,62 121.6,61.55 C56.2@121.408,61.358
NetC59_2: C59.2 U9.8 U9.11 | length 7.4
  Top Layer w0.3: v1(115,47.3) C59.2@115.7,47.3 ; 116.112,47.238 U9.8@117.2,47.238 ; U9.11@119.1,47.15 119.1,46.875 119.346,46.629 119.471,46.629 v1(119.5,46.6)
  Bottom Layer w0.3: v1(115,47.3) 118.8,47.3 v1(119.5,46.6)
NetC66_2: C66.2 U11.8 U11.11 | length 5.9
  Top Layer w0.3: v1(129.3,51.7) 129.575,51.425 129.575,51.025 U11.11@129.6,51 ; U11.8@131.5,50.912 v1(132.4,50.912) 132.429,50.883 133.059,50.883 C66.2@133.088,50.912
  Bottom Layer w0.3: v1(129.3,51.7) 130.088,50.912 v1(132.4,50.912)
NetD1_1: D1.1 R13.2 | length 2.1
  Top Layer w0.3: D1.1@115.7,76.7 115.7,77.52 115.88,77.7 R13.2@115.9,77.7 ; D1.1@115.8,76.5 115.8,76.7 R13.2@115.8,77.52
NetD2_1: D2.1 R12.2 | length 1.2
  Top Layer w0.3: R12.2@93.2,84.7 93.212,84.688 94.388,84.688 D2.1@94.4,84.675
NetD3_1: D3.1 R15.2 | length 1.2
  Top Layer w0.5: R15.2@107.3,101.5 D3.1@108.5,101.5
NetD4_1: D4.1 R16.2 | length 1.2
  Top Layer w0.3: R16.2@93.2,86 D4.1@94.4,86
NetD5_1: D5.1 R17.2 | length 1.2
  Top Layer w0.3: R17.2@93.2,83.4 93.212,83.388 94.388,83.388 D5.1@94.4,83.375
NetD6_2: D6.2 R19.1 | length 1.2
  Top Layer w0.3: R19.1@101.225,59.375 D6.2@101.225,60.575
NetD7_2: D7.2 R22.1 T1.3 | length 5.8
  Top Layer w0.3: T1.3@104.96,44.255 104.96,44.745 104.25,45.455 D7.2@104.25,47.4 104.537,47.4 104.637,47.5 104.637,48.467 105.3,49.13 R22.1@105.35,49.13
NetD8_1: D8.1 R23.1 T1.1 | length 5.9
  Top Layer w0.3: R23.1@109.05,49.13 109.1,49.13 110.163,48.067 110.163,47.5 110.262,47.4 D8.1@110.55,47.4 110.55,45.255 110.04,44.745 T1.1@110.04,44.255
NetD11_1: D11.1 R48.2 | length 1.2
  Top Layer w0.5: D11.1@128.4,92 R48.2@129.6,92
NetD12_1: D12.1 R49.2 | length 1.2
  Top Layer w0.5: D12.1@128.4,93.3 R49.2@129.6,93.3
NetD13_1: D13.1 R50.2 | length 1.2
  Top Layer w0.5: D13.1@128.4,94.6 R50.2@129.6,94.6
NetD14_1: D14.1 R55.2 | length 1.2
  Top Layer w0.5: R55.2@131.1,57.6 D14.1@132.3,57.6
NetIC1_1: IC1.1 R1.2 | length 1.5
  Top Layer w0.3: R1.2@98.775,95.7 98.775,94.876 98.951,94.7 98.975,94.7 99.049,94.626 IC1.1@99.049,94.3
NetIC1_3: IC1.3 R2.2 | length 1.6
  Top Layer w0.3: IC1.3@97.149,94.3 97.149,94.6 97.399,94.85 R2.2@97.399,95.75
NetIC3_10: IC3.10 R30.1 | length 4.3
  Top Layer w0.3: R30.1@93.7,60.2 93.723,60.177 93.723,55.923 IC3.10@93.745,55.9
NetIC3_11: IC3.11 R32.1 | length 3.1
  Top Layer w0.3: R32.1@92.4,59 92.438,58.962 92.438,55.938 IC3.11@92.475,55.9
NetIC3_14: IC3.14 R29.1 | length 1.8
  Top Layer w0.3: R29.1@88.57,57.675 88.618,57.628 88.618,55.948 IC3.14@88.665,55.9
NetP1_2: P1.2 R2.1 | length 1.7
  Top Layer w0.3: R2.1@97.399,97.15 97.537,97.288 P1.2@97.537,98.79
NetP1_3: P1.3 R1.1 | length 1.9
  Top Layer w0.3: P1.3@98.187,98.79 98.187,97.612 98.649,97.15 R1.1@98.699,97.15
NetR4_2: R4.2 U2.21 | length 3.5
  Top Layer w0.3: R4.2@102.7,66.2 102.75,66.2 103.25,66.7 U2.21@103.25,69.4
NetR5_2: R5.2 U2.22 | length 3.4
  Top Layer w0.3: U2.22@103.75,69.4 103.75,67.4 104.3,66.85 R5.2@104.3,66.2
NetR6_2: R6.2 U2.23 | length 4
  Top Layer w0.3: U2.23@104.25,69.4 104.25,68 105.77,66.48 105.77,66.38 105.95,66.2 R6.2@106.05,66.2
NetR38_1: R38.1 U4.3 | length 1.7
  Top Layer w0.3: R38.1@119.7,96.502 119.75,96.502 119.993,96.744 120.771,96.744 120.9,96.874 U4.3@120.9,97.229
NetR41_1: R41.1 U5.3 | length 1.7
  Top Layer w0.3: R41.1@123.5,96.5 123.55,96.5 123.794,96.744 124.571,96.744 124.7,96.874 U5.3@124.7,97.229
NetR45_1: R45.1 U6.3 | length 1.7
  Top Layer w0.3: R45.1@115.9,96.502 115.95,96.502 116.13,96.682 116.363,96.682 116.46,96.779 116.971,96.779 117.1,96.909 U6.3@117.1,97.229
NetR51_1: R51.1 U7.3 | length 1.7
  Top Layer w0.3: R51.1@112.1,96.502 112.15,96.502 112.393,96.744 113.171,96.744 113.3,96.874 U7.3@113.3,97.229
NetR57_1: R57.1 R59.2 U9.9 | length 2.8
  Top Layer w0.3: R59.2@117.7,44.5 R57.1@117.7,45.8 117.7,46.5 118.05,46.85 118.075,46.85 118.1,46.875 U9.9@118.1,47.15
NetR60_1: R60.1 R61.2 U11.9 | length 2.8
  Top Layer w0.3: U11.9@130.6,51 130.6,51.275 130.8,51.475 R60.1@130.8,52.4 R61.2@130.8,53.7
NRST: C13.1 J2.2 U2.7 | length 23.2
  Top Layer w0.3: J2.2@86.6,84.54 89.36,87.3 v1(91.1,87.3) ; C13.1@97.3,75.3 97.3,75.35 97.48,75.53 97.889,75.53 97.959,75.6 v1(98,75.6) 98.041,75.6 98.191,75.75 U2.7@99.4,75.75
  Bottom Layer w0.3: v1(91.1,87.3) 93.4,85 93.4,79.1 96.9,75.6 v1(98,75.6)
PHAPOL: IC2.14 R24.1 R26.1 | length 5.2
  Top Layer w0.3: IC2.14@110.3,58.18 110.3,57.749 110.618,57.431 113.648,57.431 R24.1@113.65,57.43 R26.1@113.65,56.13
reg_input: C52.2 C53.1 C54.2 C55.1 C60.2 C61.1 C62.2 C63.1 Q5.2 Q6.2 R54.1 U8.1 U9.2 U9.3 U10.1 U11.2 U11.3 | length 46.7
  Top Layer w0.3: 119.8,48.3 119.8,48.075 119.825,48.05 U9.2@120,48.05 ; U11.3@128.7,49.6 128.7,49.7 cw(c128.9,49.7) 128.9,49.9
  Top Layer w0.7: 119.8,48.3 C55.1@121.5,48.3 C54.2@122.8,48.3 122.81,48.3 122.83,48.32 122.83,48.33 123.9,49.4 123.9,51.1 ; Q6.2@121.132,58.05 121.14,58.05 121.19,58 121.19,56.73 121.2,56.72 R54.1@121.2,56.7 121.22,56.68 121.22,56.67 121.24,56.65 121.25,56.65 122.4,55.5 122.95,55.5 123,55.45 123,52 123.9,51.1 ; 128.9,49.9 C63.1@127.2,49.9 C62.2@125.9,49.9 125.1,49.9 ; C61.1@132.095,29.22 C61.1@132.075,29.2 C60.2@132.075,30.5 132.075,30.51 130.985,31.6 U10.1@127.84,31.6 127.94,31.7 127.94,39.6 U8.1@128.04,39.7 128.04,39.854 126.6,41.294 C52.2@126.6,42.8 C53.1@126.6,44.168 126.6,46.7 125.1,48.2 125.1,49.9 ; 123.9,51.1 125.1,49.9
SCK: IC2.4 R4.1 TP3.1 | length 6.7
  Top Layer w0.3: R4.1@102.7,64.8 TP3.1@102.7,63.7 105.52,60.88 IC2.4@107.1,60.88
SD_Contactors: C41.2 C42.2 C46.2 C47.2 C49.2 D3.2 J1.6 Q1.2 Q3.2 Q4.2 R10.1 R36.2 R37.2 R43.2 R44.2 R47.2 | length 90.4
  Top Layer w0.5: D3.2@110.1,101.5 v1(110.9,101.5) ; R10.1@117.8,60.1 v1(118.3,60.1)
  Top Layer w0.75: v2(109.4,91.3) 110.177,91.3 110.25,91.227 110.8,91.777 C49.2@110.8,92.602 R47.2@110.8,93.777
  Top Layer w1: v2(112,87.7) v2(113.2,87.7) v2(114,86.9) v1(124.5,76.4) J1.6@128,76.4 ; Q3.2@114.05,91.302 114.05,91.352 113.4,92.002 C47.2@113.4,92.5 113.502,92.602 C46.2@114.6,92.602 R43.2@114.6,93.901 114.7,94.002 R44.2@114.7,95.2 v2(114.7,97.3) ; C42.2@117.2,92.5 C42.2@117.25,92.5 ; Q1.2@117.75,91.302 117.75,91.352 117.33,91.771 117.33,92.42 C42.2@117.25,92.5 ; v2(118.5,97.1) v2(118.5,96.1) R37.2@118.5,95.2 118.5,94.002 R36.2@118.4,93.901 C41.2@118.4,92.602 118.349,92.551 117.301,92.551 C42.2@117.25,92.5
  Bottom Layer w0.5: v1(118.3,60.1) 118.3,65.35 124.5,71.55 v1(124.5,76.4)
  Bottom Layer w1.5: v1(110.9,101.5) 113.2,101.5 114.7,100 114.7,94.8 113.102,93.202 ; v2(114,86.9) v2(113.2,87.7) v2(112,87.7) 109.6,90.1 109.6,92.2 110.602,93.202 113.102,93.202 ; v2(118.5,97.1) v2(118.5,96.1) 115.602,93.202 113.102,93.202
  other v2: 114.7,96.2
SD_Contactors_mcu: C14.1 R10.2 R11.2 U2.27 | length 16.8
  Top Layer w0.3: U2.27@106.25,69.4 106.25,68.091 106.3,68.041 v1(106.3,68) ; R10.2@116.4,60.1 R11.2@116.4,61.4 C14.1@116.4,62.7 ; C14.1@116.4,62.6 v1(116.4,63.3)
  Bottom Layer w0.3: v1(106.3,68) 111.7,68 v1(116.4,63.3)
Shunt_N: C30.1 C31.1 C32.1 C37.2 C38.1 IC3.2 IC3.8 J4.3 | length 30.5
  Top Layer w0.3: v1(89.87,42.475) C37.2@89.87,43.275 C38.1@89.87,44.575
  Top Layer w0.5: IC3.2@87.395,46.45 87.383,46.438 87.383,44.588 C31.1@87.37,44.575 C32.1@87.37,43.275 C30.1@87.37,41.975 v1(88.07,41.975) ; J4.3@89,29.6 v1(89,31.2) ; IC3.8@95.015,46.45 95.07,46.395 v1(95.07,45.075)
  Bottom Layer w0.5: v1(89,31.2) 89.6,31.8 89.6,38.845 87.7,40.745 87.7,41.605 v1(88.07,41.975) 89.37,41.975 v1(89.87,42.475) 92.47,45.075 v1(95.07,45.075)
Shunt_N_Kelvin: J4.2 R35.1 | length 3.8
  Top Layer w0.3: J4.2@92,39 92.443,39.443 92.443,40.078 92.485,40.12 92.52,40.12 93.823,41.423 93.823,41.828 R35.1@93.97,41.975
Shunt_P_Kelvin: J4.1 R33.1 | length 5.3
  Top Layer w0.3: J4.1@89,39 89,39.635 89.485,40.12 89.52,40.12 91.375,41.975 R33.1@92.67,41.975
SWCLK: J2.5 U2.49 | length 27.7
  Top Layer w0.3: J2.5@86.6,92.16 91.815,92.16 94.075,89.9 100.1,89.9 v1(100.5,89.5) ; v1(108.7,82) 108.7,81.959 108.75,81.909 U2.49@108.75,80.6
  Bottom Layer w0.3: v1(100.5,89.5) 101.2,89.5 v1(108.7,82)
SWDIO: J2.4 U2.46 | length 31.7
  Top Layer w0.3: J2.4@86.6,89.62 86.931,89.62 87.451,89.1 99.8,89.1 v1(100.4,88.5) ; U2.46@110.6,77.75 111.909,77.75 111.959,77.8 v1(112,77.8)
  Bottom Layer w0.3: v1(100.4,88.5) 101,88.5 111.671,77.829 111.971,77.829 v1(112,77.8)
SWO: J2.3 U2.55 | length 24.7
  Top Layer w0.3: J2.3@86.6,87.08 86.931,87.08 87.951,88.1 99.8,88.1 v1(100.4,87.5) ; U2.55@105.75,80.6 105.75,81.5 105.848,81.598 105.848,81.666 106.089,81.907 106.471,81.907 v1(106.5,81.935)
  Bottom Layer w0.3: v1(100.4,87.5) 100.935,87.5 v1(106.5,81.935)
unreg_V: C51.1 C56.1 J1.15 Q5.1 Q6.3 R53.2 R54.2 R56.2 | length 16.5
  Top Layer w0.5: R54.2@122.6,56.7 R53.2@126.2,56.7 C51.1@126.2,55.4 Q5.1@124.9,55.4 ; R54.2@122.608,56.708 122.68,56.78 122.68,57.022 122.9,57.241 122.9,58.557 122.932,58.589 122.932,58.85 123.082,59 Q6.3@123.132,59
  Top Layer w0.7: Q6.3@123.082,59 122.8,59.282 C56.1@122.8,61.3 122.82,61.32 122.82,61.33 122.92,61.33 123.5,61.91 R56.2@123.5,62.6 ; R56.2@123.52,62.63 123.64,62.63 123.91,62.9 J1.15@127.075,62.9
USB_D_N: IC1.4 U2.44 | length 23.4
  Top Layer w0.3: v1@97.25,90.925 97.25,91.649 IC1.4@97.275,91.674 ; v1(109.3,76.712) 109.329,76.74 109.69,76.74 109.7,76.75 U2.44@110.6,76.75
  Bottom Layer w0.3: v1(97.275,90.9) 97.974,90.201 97.974,84.383 105.545,76.812 109.067,76.812 109.092,76.787 109.184,76.787 109.259,76.712 v1(109.3,76.712)
USB_D_P: IC1.6 U2.45 | length 22.8
  Top Layer w0.3: IC1.6@99.075,91.774 99.1,91.749 v1@99.1,90.925 ; v1(109.3,77.289) 109.329,77.26 109.69,77.26 109.7,77.25 U2.45@110.6,77.25
  Bottom Layer w0.3: v1(99.075,90.9) 98.376,90.201 98.376,84.549 105.712,77.214 109.184,77.214 109.259,77.289 v1(109.3,77.289)
XCVRMD: IC2.16 R25.1 R27.2 | length 4.3
  Top Layer w0.3: IC2.16@111.3,58.18 111.3,57.905 112.875,57.905 113.65,58.68 R25.1@113.65,58.73 R27.2@113.65,60.03
pads on no net: IC2.7 IC2.15 IC2.18 IC2.19 IC2.22 IC2.23 IC2.24 IC2.26 IC2.27 IC2.28 IC2.29 IC2.31 IC2.32 IC3.4 IC4.5 J1.16 J1.17 J3.2 J3.4 J4.4 J4.5 J4.6 MH1. MH2. MH3. MH4. P1.4 P1.6 T1.2 T1.5 U2.2 U2.3 U2.4 U2.8 U2.9 U2.10 U2.11 U2.14 U2.15 U2.17 U2.24 U2.25 U2.26 U2.28 U2.29 U2.30 U2.35 U2.37 U2.50 U2.51 U2.52 U2.53 U2.54 U2.56 U9.1 U9.5 U9.6 U9.7 U11.1 U11.5 U11.6 U11.7 U12_DATA.5 U12_Drive.5

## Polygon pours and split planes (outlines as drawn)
GND on Top Layer "GND_L01_P016" (solid, remove dead copper, pour order 16): 86.106,103.412 ccw(c86.106,102.112) 84.806,102.112 84.806,75.512 ccw(c85.606,75.512) 85.606,74.712 100.406,74.712 cw(c100.406,74.512) 100.606,74.512 cw(c100.406,74.512) 100.406,74.312 85.506,74.312 ccw(c85.506,73.612) 84.806,73.612 84.806,54.112 ccw(c85.706,54.112) 85.706,53.212 95.506,53.212 ccw(c95.506,53.812) 96.106,53.812 96.106,67.812 cw(c97.106,67.812) 97.106,68.812 97.406,68.812 ccw(c97.406,69.412) 98.006,69.412 98.006,70.836 cw(c98.094,70.836) 98.094,70.924 100.406,70.912 cw(c100.356,70.762) 100.506,70.712 cw(c100.406,70.712) 100.406,70.612 98.506,70.612 ccw(c98.506,70.412) 98.306,70.412 98.306,69.412 cw(c97.406,69.412) 97.406,68.512 97.306,68.512 ccw(c97.356,67.562) 96.406,67.512 96.406,53.812 ccw(c97.006,53.812) 97.006,53.212 100.328,53.212 cw(c100.328,53.122) 100.417,53.122 100.417,41.6 ccw(c101.106,41.6) 101.106,40.912 116.606,40.912 cw(c116.606,40.612) 116.906,40.612 116.906,16.612 ccw(c117.306,16.612) 117.306,16.212 134.306,16.212 ccw(c134.306,18.012) 136.106,18.012 136.106,101.812 ccw(c134.506,101.812) 134.506,103.412
GND on Top Layer "GND_L01_P001" (solid, pour order 1): 133.04,54.59 127.94,54.59 ccw(c128.06,51.87) 125.34,51.75 125.34,49.105 ccw(c127.88,49.105) 127.88,46.565 129.265,46.565 cw(c129.265,45.59) 130.24,45.59 130.24,43.29 ccw(c130.74,43.29) 130.74,42.79 131.4,42.79 ccw(c131.67,45.56) 134.44,45.29 134.44,53.19 ccw(c133.04,53.19)
GND on Top Layer "GND_L01_P000" (solid, pour order 0): 115.7,43.6 120.8,43.6 ccw(c120.68,46.32) 123.4,46.44 123.4,49.085 ccw(c120.86,49.085) 120.86,51.625 119.475,51.625 cw(c119.475,52.6) 118.5,52.6 118.5,54.9 ccw(c118,54.9) 118,55.4 ccw(c117.437,52.263) 114.3,52.826 114.3,45 ccw(c115.7,45)
GND on Top Layer "GND_L01_P006" (solid, pour order 6): 108.2,62.4 ccw(c108.2,61.9) 107.7,61.9 107.7,59.3 ccw(c108.2,59.3) 108.2,58.8 111,58.8 ccw(c111,59.2) 111.4,59.2 111.4,62 ccw(c111,62) 111,62.4 109.7,62.4
no net on Top Overlay "NONET_L-01_P-001" (hatched 45Degree grid 2 track 0.1): 85.07,53 100.2,53 100.2,40.7 116.6,40.7 116.6,23.9 85.07,23.9 85.07,27.9 112.6,27.9 112.6,36.7 96.07,36.7 96.07,49 85.07,49
no net on Bottom Overlay "NONET_L-01_P-001" (hatched 45Degree grid 2 track 0.1): 85.07,53 100.2,53 100.2,40.7 116.6,40.7 116.6,23.9 85.07,23.9 85.07,27.9 112.6,27.9 112.6,36.7 96.07,36.7 96.07,49 85.07,49
GND on Layer 1 "GND_L02_P014" (solid, remove dead copper, pour order 14): 86.1,103.4 ccw(c86.1,102.1) 84.8,102.1 84.8,75.5 ccw(c85.6,75.5) 85.6,74.7 100.4,74.7 cw(c100.4,74.5) 100.6,74.5 cw(c100.4,74.5) 100.4,74.3 85.5,74.3 ccw(c85.5,73.6) 84.8,73.6 84.8,54.1 ccw(c85.7,54.1) 85.7,53.2 95.5,53.2 ccw(c95.5,53.8) 96.1,53.8 96.1,67.8 cw(c97.1,67.8) 97.1,68.8 97.4,68.8 ccw(c97.4,69.4) 98,69.4 98,70.824 cw(c98.088,70.824) 98.088,70.912 100.4,70.9 cw(c100.35,70.75) 100.5,70.7 cw(c100.4,70.7) 100.4,70.6 98.5,70.6 ccw(c98.5,70.4) 98.3,70.4 98.3,69.4 cw(c97.4,69.4) 97.4,68.5 97.3,68.5 ccw(c97.35,67.55) 96.4,67.5 96.4,53.8 ccw(c97,53.8) 97,53.2 100.322,53.2 cw(c100.322,53.111) 100.412,53.111 100.412,41.588 ccw(c101.1,41.588) 101.1,40.9 116.6,40.9 cw(c116.6,40.6) 116.9,40.6 116.9,16.6 ccw(c117.3,16.6) 117.3,16.2 134.3,16.2 ccw(c134.3,18) 136.1,18 136.1,101.8 ccw(c134.5,101.8) 134.5,103.4
3V3 on Layer 2 "3V3_L03_P018" (solid, remove dead copper, pour order 18): 86.1,103.4 ccw(c86.1,102.1) 84.8,102.1 84.8,75.5 ccw(c85.6,75.5) 85.6,74.7 100.4,74.7 cw(c100.4,74.5) 100.6,74.5 cw(c100.4,74.5) 100.4,74.3 85.5,74.3 ccw(c85.5,73.6) 84.8,73.6 84.8,54.1 ccw(c85.7,54.1) 85.7,53.2 95.5,53.2 ccw(c95.5,53.8) 96.1,53.8 96.1,67.8 cw(c97.1,67.8) 97.1,68.8 97.4,68.8 ccw(c97.4,69.4) 98,69.4 98,70.824 cw(c98.088,70.824) 98.088,70.912 100.4,70.9 cw(c100.35,70.75) 100.5,70.7 cw(c100.4,70.7) 100.4,70.6 98.5,70.6 ccw(c98.5,70.4) 98.3,70.4 98.3,69.4 cw(c97.4,69.4) 97.4,68.5 97.3,68.5 ccw(c97.35,67.55) 96.4,67.5 96.4,53.8 ccw(c97,53.8) 97,53.2 100.322,53.2 cw(c100.322,53.111) 100.412,53.111 100.412,41.588 ccw(c101.1,41.588) 101.1,40.9 116.6,40.9 cw(c116.6,40.6) 116.9,40.6 116.9,16.6 ccw(c117.3,16.6) 117.3,16.2 134.3,16.2 ccw(c134.3,18) 136.1,18 136.1,101.8 ccw(c134.5,101.8) 134.5,103.4
GND on Bottom Layer "GND_L04_P017" (solid, remove dead copper, pour order 17): 86.106,103.412 ccw(c86.106,102.112) 84.806,102.112 84.806,75.512 ccw(c85.606,75.512) 85.606,74.712 100.406,74.712 cw(c100.406,74.512) 100.606,74.512 cw(c100.406,74.512) 100.406,74.312 85.506,74.312 ccw(c85.506,73.612) 84.806,73.612 84.806,54.112 ccw(c85.706,54.112) 85.706,53.212 95.506,53.212 ccw(c95.506,53.812) 96.106,53.812 96.106,67.812 cw(c97.106,67.812) 97.106,68.812 97.406,68.812 ccw(c97.406,69.412) 98.006,69.412 98.006,70.836 cw(c98.094,70.836) 98.094,70.924 100.406,70.912 cw(c100.356,70.762) 100.506,70.712 cw(c100.406,70.712) 100.406,70.612 98.506,70.612 ccw(c98.506,70.412) 98.306,70.412 98.306,69.412 cw(c97.406,69.412) 97.406,68.512 97.306,68.512 ccw(c97.356,67.562) 96.406,67.512 96.406,53.812 ccw(c97.006,53.812) 97.006,53.212 100.328,53.212 cw(c100.328,53.122) 100.417,53.122 100.417,41.6 ccw(c101.106,41.6) 101.106,40.912 116.606,40.912 cw(c116.606,40.612) 116.906,40.612 116.906,16.612 ccw(c117.306,16.612) 117.306,16.212 134.306,16.212 ccw(c134.306,18.012) 136.106,18.012 136.106,101.812 ccw(c134.506,101.812) 134.506,103.412

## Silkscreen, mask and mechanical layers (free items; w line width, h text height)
Top Overlay:
  drawing of 32 lines, arcs and shapes, not listed
  text "Shutdown" at 104.2,102.2 h1
  text "Hard work" at 102.55,98.25 h0.75
  text "Beats talent" at 102.55,97.25 h0.75
  text "Pre C" at 132.15,94.25 h0.75
  text "Pos C" at 132.15,92.95 h0.75
  text "Neg C" at 132.15,91.6 h0.75
  text "GPIO LEDs" at 89.6,86.8 h1
  text "1" at 96.8,85.6 h1
  text "2" at 89.8,84.2 h1
  text "3" at 96.7,82.9 h1
  text "Status" at 114.35,77.55 h0.75 r270
  text "SCK" at 102.55,62.95 h0.5 r270
  text "MISO" at 104.05,62.95 h0.5 r270
  text "MOSI" at 105.85,62.95 h0.5 r270
  text "CSB" at 97.7,61 h1
  text "3.3V" at 131.8,55.9 h1
  text "6822" at 102.35,54.7 h0.5
  text "State" at 102.35,54.05 h0.5
  text "GLV" at 96.1,53.6 h2
  text "4mm" at 97.65,35.45 h1
  text "TS" at 97.4,28.5 h2
  text "Drake" at 118.5,20.8 h1
  text "AD Mainboard" at 93.9,20 h1
  text "Vogelpohl" at 118.5,19.433 h1
  text "March 2025" at 93.8,18.9 h0.5
Bottom Overlay:
  drawing of 16 lines, arcs and shapes, not listed
  text "If you're reading this" at 135.146,89.062 h1.52
  text "Take a break" at 135.246,87.054 h1.52
  text "GLV" at 99.7,53.5 h2
  text "4mm" at 100.25,35.45 h1
  text "TS" at 100.9,28.5 h2
Mechanical 1:
  lines w0.254: 84.6,17.27 ccw(c85.87,17.27) 85.87,16 117.2,16 135.03,16 ccw(c135.03,17.27) 136.3,17.27 136.3,102.33 ccw(c135.03,102.33) 135.03,103.6 85.87,103.6 ccw(c85.87,102.33) 84.6,102.33 84.6,17.27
